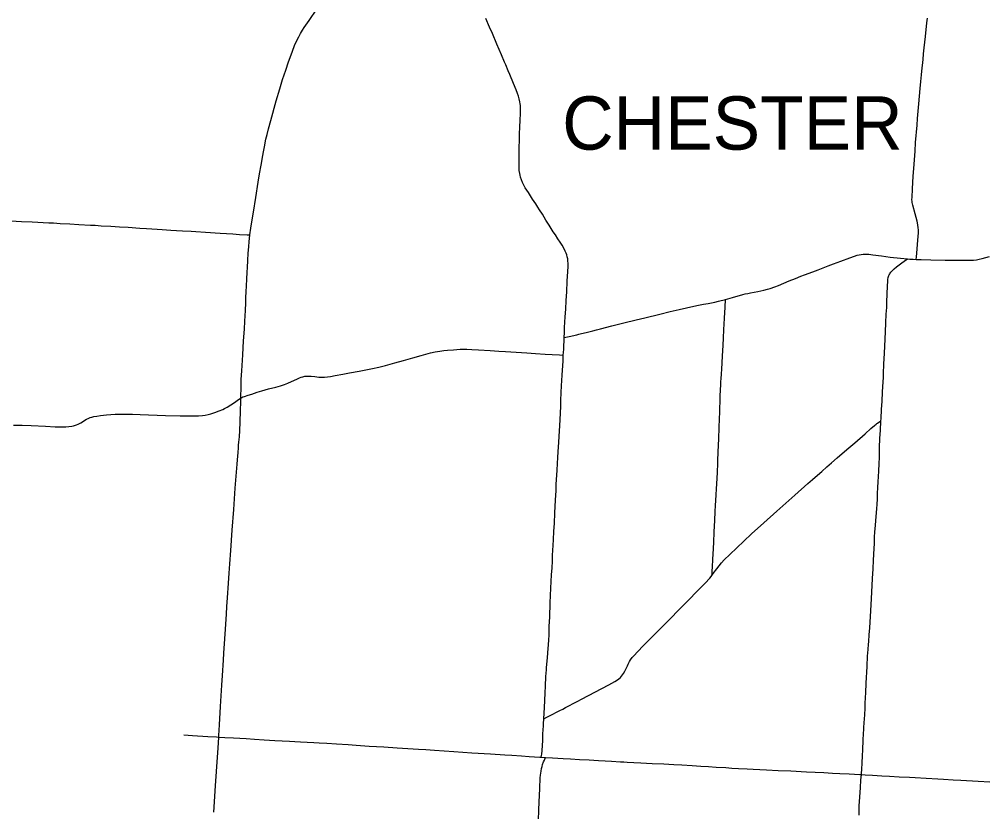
# Model space of a CAD drawing. Extents: x 9078 to 9739, y 4248 to 4966.
# Drawn here: x 9549.3 to 9630.7, y 4427 to 4493.9 of the extents above; entities that cross this region are included whole.
import ezdxf

# ---------------------------------------------------------------- set-up
doc = ezdxf.new("R2010")
doc.units = 0
for name, color, linetype in [('GM_X_County_Road', 7, 'Continuous'), ('GM_X_State_Route', 7, 'Continuous'), ('GM_X_Township_Road', 7, 'Continuous'), ('GM_X_Township_Text', 7, 'Continuous')]:
    doc.layers.add(name, color=color, linetype=linetype)

msp = doc.modelspace()

# ---------------------------------------------------------------- linework, layer by layer
at = {"layer": 'GM_X_County_Road'}
for points in [[(9625.055, 4473.625), (9625.073, 4473.844), (9625.128, 4474.495), (9625.167, 4474.902), (9625.226, 4475.555), (9625.246, 4475.882), (9625.245, 4476.127), (9625.234, 4476.29), (9625.2, 4476.534), (9625.132, 4476.854), (9624.971, 4477.489), (9624.784, 4478.203), (9624.729, 4478.442), (9624.715, 4478.523), (9624.702, 4478.685), (9624.705, 4478.849), (9624.749, 4479.585), (9624.808, 4480.646), (9624.852, 4481.297), (9624.96, 4482.766), (9625.012, 4483.502), (9625.13, 4484.971), (9625.173, 4485.543), (9625.271, 4486.767), (9625.394, 4488.072), (9625.447, 4488.642), (9625.507, 4489.212), (9625.541, 4489.538), (9625.636, 4490.515), (9625.683, 4491.004), (9625.735, 4491.493), (9625.787, 4491.981), (9625.839, 4492.468), (9625.963, 4493.608), (9626.009, 4494.015)], [(9548.102, 4476.916), (9549.494, 4476.839), (9550.395, 4476.793), (9551.788, 4476.726), (9552.197, 4476.707), (9552.77, 4476.673), (9553.589, 4476.629), (9554.326, 4476.587), (9555.308, 4476.532), (9555.718, 4476.507), (9556.208, 4476.476), (9557.025, 4476.426), (9557.761, 4476.389), (9558.497, 4476.338), (9559.48, 4476.278), (9560.052, 4476.235), (9560.952, 4476.177), (9561.361, 4476.15), (9562.097, 4476.103), (9562.588, 4476.071), (9563.079, 4476.04), (9563.815, 4475.998), (9564.225, 4475.978), (9565.044, 4475.929), (9566.271, 4475.848), (9567.335, 4475.777), (9567.907, 4475.734), (9568.563, 4475.697), (9568.791, 4475.69)], [(9608.942, 4470.226), (9609.547, 4470.397), (9610.41, 4470.66), (9610.602, 4470.708), (9610.834, 4470.755), (9611.052, 4470.796), (9611.696, 4470.923), (9612.178, 4471.024), (9612.497, 4471.103), (9612.732, 4471.174), (9613.12, 4471.308), (9613.426, 4471.427), (9614.336, 4471.804), (9614.866, 4472.023), (9615.321, 4472.202), (9615.627, 4472.319), (9616.317, 4472.581), (9616.778, 4472.753), (9617.62, 4473.074), (9618.08, 4473.248), (9618.694, 4473.479), (9619.463, 4473.764), (9619.849, 4473.904), (9620.083, 4473.981), (9620.242, 4474.021), (9620.404, 4474.048), (9620.567, 4474.066), (9620.813, 4474.075), (9621.059, 4474.062), (9621.385, 4474.025), (9622.116, 4473.921), (9622.849, 4473.827), (9623.745, 4473.72), (9624.317, 4473.664)], [(9625.055, 4473.625), (9625.463, 4473.61), (9626.283, 4473.588), (9627.514, 4473.566), (9628.006, 4473.568), (9629.154, 4473.55), (9629.647, 4473.552), (9629.893, 4473.565), (9630.137, 4473.592), (9630.38, 4473.634), (9630.619, 4473.69), (9631.249, 4473.875)], [(9624.317, 4473.664), (9624.52, 4473.649), (9624.808, 4473.634), (9625.055, 4473.625)], [(9595.329, 4467.041), (9595.75, 4467.116), (9596.391, 4467.261), (9596.551, 4467.298), (9596.791, 4467.355), (9597.19, 4467.453), (9597.747, 4467.597), (9598.065, 4467.68), (9598.383, 4467.762), (9599.338, 4468.004), (9600.373, 4468.268), (9601.41, 4468.521), (9602.129, 4468.696), (9603.407, 4469.005), (9604.286, 4469.219), (9605.046, 4469.408), (9605.647, 4469.531), (9606.531, 4469.719), (9607.094, 4469.833), (9607.499, 4469.902), (9608.064, 4470.014), (9608.372, 4470.086), (9608.942, 4470.226)], [(9595.255, 4465.533), (9595.271, 4465.759), (9595.284, 4466.032), (9595.329, 4467.041)], [(9568.02, 4461.916), (9568.115, 4461.973), (9568.193, 4462.01), (9568.32, 4462.053), (9568.635, 4462.149), (9568.951, 4462.253), (9569.407, 4462.414), (9569.797, 4462.532), (9570.348, 4462.683), (9570.983, 4462.843), (9571.38, 4462.951), (9571.692, 4463.054), (9571.998, 4463.173), (9572.299, 4463.305), (9572.741, 4463.519), (9572.962, 4463.621), (9573.113, 4463.677), (9573.268, 4463.72), (9573.427, 4463.749), (9573.589, 4463.764), (9573.748, 4463.765), (9573.881, 4463.761), (9573.954, 4463.757), (9574.272, 4463.724), (9574.599, 4463.688), (9574.847, 4463.675), (9575.094, 4463.679), (9575.34, 4463.7), (9575.585, 4463.734), (9575.988, 4463.811), (9576.631, 4463.936), (9577.195, 4464.037), (9578.002, 4464.181), (9579.125, 4464.417), (9579.686, 4464.537), (9580.244, 4464.673), (9580.639, 4464.781), (9581.033, 4464.892), (9581.743, 4465.088), (9582.534, 4465.304), (9583.242, 4465.509), (9583.635, 4465.62), (9584.03, 4465.722), (9584.429, 4465.806), (9584.831, 4465.876), (9585.154, 4465.922), (9585.479, 4465.957), (9585.968, 4465.997), (9586.539, 4466.031), (9586.865, 4466.039), (9587.11, 4466.036), (9587.518, 4466.018), (9588.09, 4465.982), (9589.072, 4465.92), (9589.808, 4465.878), (9590.379, 4465.835), (9591.279, 4465.783), (9592.179, 4465.728), (9592.915, 4465.684), (9593.732, 4465.632), (9594.305, 4465.598), (9594.937, 4465.553), (9595.255, 4465.533)], [(9566.153, 4433.28), (9566.654, 4433.24), (9567.388, 4433.201), (9567.927, 4433.169), (9568.481, 4433.144), (9569.177, 4433.102), (9569.993, 4433.052), (9570.883, 4432.992), (9571.515, 4432.95), (9572.142, 4432.918), (9572.584, 4432.895), (9573.045, 4432.872), (9573.626, 4432.84), (9574.193, 4432.808), (9574.636, 4432.784), (9575.295, 4432.757), (9576.093, 4432.715), (9577.075, 4432.637), (9577.767, 4432.591), (9578.858, 4432.517), (9580.087, 4432.439), (9581.233, 4432.363), (9582.134, 4432.3), (9583.036, 4432.246), (9583.64, 4432.213), (9584.378, 4432.163), (9586.015, 4432.057), (9587.536, 4431.953), (9589.091, 4431.855), (9590.319, 4431.775), (9590.892, 4431.736), (9591.709, 4431.68), (9592.364, 4431.634), (9593.264, 4431.577), (9593.396, 4431.57)], [(9593.396, 4431.57), (9593.418, 4431.569), (9593.757, 4431.55)], [(9593.757, 4431.55), (9594.342, 4431.516), (9595.246, 4431.455), (9595.85, 4431.423), (9596.621, 4431.379), (9597.429, 4431.339), (9598.223, 4431.294), (9598.79, 4431.263), (9599.311, 4431.236), (9600.072, 4431.191), (9600.378, 4431.178), (9600.641, 4431.156), (9601.214, 4431.126), (9601.787, 4431.099), (9602.768, 4431.047), (9603.755, 4431.009), (9604.593, 4430.96), (9605.271, 4430.924), (9606.146, 4430.862), (9606.862, 4430.823), (9607.517, 4430.784), (9608.172, 4430.741), (9608.991, 4430.693), (9609.481, 4430.662), (9610.052, 4430.633), (9610.788, 4430.594), (9611.279, 4430.568), (9612.426, 4430.508), (9613.409, 4430.464), (9614.473, 4430.414), (9615.784, 4430.343), (9617.245, 4430.274), (9617.976, 4430.234), (9618.614, 4430.207), (9619.382, 4430.171), (9620.309, 4430.109), (9620.432, 4430.103)], [(9620.432, 4430.103), (9620.76, 4430.087), (9621.358, 4430.051), (9622.161, 4430.006), (9622.794, 4429.975), (9623.624, 4429.926), (9624.489, 4429.882), (9624.958, 4429.855), (9625.889, 4429.797), (9626.871, 4429.749), (9627.367, 4429.721), (9628.179, 4429.674), (9628.833, 4429.639), (9630.302, 4429.555), (9631.284, 4429.494), (9632.431, 4429.433), (9633.004, 4429.396), (9633.823, 4429.349), (9634.059, 4429.334)]]:
    msp.add_lwpolyline(points, dxfattribs=at)
at = {"layer": 'GM_X_State_Route'}
msp.add_lwpolyline([(9565.734, 4426.937), (9565.882, 4429.147), (9565.967, 4430.373), (9566.019, 4431.192), (9566.099, 4432.337), (9566.153, 4433.28), (9566.16, 4433.401), (9566.215, 4434.302), (9566.314, 4435.857), (9566.425, 4437.657), (9566.47, 4438.476), (9566.548, 4439.785), (9566.587, 4440.358), (9566.669, 4441.582), (9566.722, 4442.401), (9566.797, 4443.66), (9566.838, 4444.319), (9566.885, 4445.039), (9566.972, 4446.274), (9567.028, 4447.129), (9567.08, 4447.921), (9567.167, 4449.025), (9567.297, 4450.742), (9567.414, 4452.496), (9567.481, 4453.412), (9567.553, 4454.308), (9567.657, 4455.645), (9567.702, 4456.336), (9567.733, 4456.707), (9567.779, 4457.319), (9567.81, 4457.71), (9567.829, 4457.931), (9567.853, 4458.175), (9567.892, 4458.626), (9567.923, 4459.182), (9567.96, 4459.883), (9567.996, 4460.866), (9568.015, 4461.604), (9568.02, 4461.916), (9568.039, 4462.916), (9568.058, 4463.491), (9568.092, 4464.204), (9568.185, 4465.553), (9568.257, 4466.747), (9568.326, 4467.746), (9568.364, 4468.401), (9568.407, 4469.301), (9568.433, 4469.957), (9568.448, 4470.449), (9568.461, 4470.858), (9568.486, 4471.432), (9568.514, 4471.923), (9568.552, 4472.578), (9568.571, 4472.905), (9568.607, 4473.559), (9568.641, 4474.132), (9568.684, 4474.705), (9568.723, 4475.113), (9568.791, 4475.69), (9568.868, 4476.252), (9568.98, 4476.982), (9569.081, 4477.63), (9569.271, 4478.846), (9569.484, 4480.141), (9569.606, 4480.869), (9569.736, 4481.596), (9569.882, 4482.403), (9569.94, 4482.726), (9570.012, 4483.128), (9570.139, 4483.77), (9570.229, 4484.17), (9570.349, 4484.648), (9570.54, 4485.361), (9571.008, 4487.019), (9571.31, 4488.042), (9571.55, 4488.827), (9571.805, 4489.607), (9572.044, 4490.306), (9572.183, 4490.692), (9572.381, 4491.23), (9572.564, 4491.687), (9572.729, 4492.062), (9572.909, 4492.431), (9573.065, 4492.72), (9573.231, 4493.004), (9573.364, 4493.211), (9573.783, 4493.819), (9574.423, 4494.772)], dxfattribs=at)
at = {"layer": 'GM_X_Township_Road'}
for points in [[(9595.329, 4467.041), (9595.344, 4467.463), (9595.365, 4467.872), (9595.416, 4468.77), (9595.453, 4469.423), (9595.496, 4470.159), (9595.541, 4470.896), (9595.588, 4471.796), (9595.632, 4472.614), (9595.65, 4473.024), (9595.652, 4473.271), (9595.642, 4473.518), (9595.623, 4473.683), (9595.589, 4473.845), (9595.544, 4474.004), (9595.488, 4474.16), (9595.423, 4474.312), (9595.312, 4474.533), (9595.149, 4474.817), (9594.978, 4475.089), (9594.803, 4475.356), (9594.581, 4475.694), (9594.405, 4475.967), (9594.23, 4476.243), (9594.059, 4476.52), (9593.767, 4476.954), (9593.486, 4477.437), (9593.233, 4477.828), (9593.104, 4478.035), (9592.928, 4478.307), (9592.659, 4478.717), (9592.302, 4479.267), (9592.043, 4479.684), (9591.924, 4479.898), (9591.819, 4480.118), (9591.725, 4480.345), (9591.646, 4480.575), (9591.604, 4480.731), (9591.573, 4480.89), (9591.539, 4481.132), (9591.519, 4481.376), (9591.511, 4481.621), (9591.515, 4482.194), (9591.532, 4483.095), (9591.551, 4483.666), (9591.566, 4484.239), (9591.586, 4484.811), (9591.613, 4485.384), (9591.637, 4485.958), (9591.647, 4486.367), (9591.639, 4486.614), (9591.623, 4486.779), (9591.594, 4486.941), (9591.536, 4487.182), (9591.467, 4487.419), (9591.386, 4487.651), (9591.266, 4487.956), (9591.045, 4488.485), (9590.729, 4489.242), (9590.603, 4489.544), (9590.389, 4490.074), (9590.297, 4490.301), (9590.045, 4490.903), (9589.652, 4491.802), (9589.265, 4492.706), (9589.033, 4493.231), (9588.704, 4493.981)], [(9622.081, 4459.98), (9622.092, 4460.157), (9622.133, 4460.976), (9622.176, 4461.629), (9622.22, 4462.447), (9622.24, 4462.856), (9622.286, 4463.671), (9622.301, 4463.998), (9622.33, 4464.771), (9622.372, 4465.715), (9622.401, 4466.288), (9622.461, 4467.517), (9622.494, 4468.255), (9622.534, 4468.991), (9622.565, 4469.564), (9622.587, 4470.056), (9622.646, 4471.367), (9622.66, 4471.776), (9622.675, 4471.939), (9622.703, 4472.101), (9622.723, 4472.181), (9622.749, 4472.258), (9622.78, 4472.334), (9622.817, 4472.407), (9622.86, 4472.477), (9622.907, 4472.544), (9623.015, 4472.667), (9623.195, 4472.835), (9623.385, 4472.991), (9623.85, 4473.328), (9624.045, 4473.477), (9624.317, 4473.664)], [(9607.804, 4446.931), (9607.816, 4447.07), (9607.837, 4447.307), (9607.85, 4447.633), (9607.885, 4448.293), (9607.91, 4448.734), (9607.958, 4449.725), (9608.004, 4450.626), (9608.054, 4451.569), (9608.092, 4452.324), (9608.118, 4452.829), (9608.17, 4453.711), (9608.197, 4454.276), (9608.217, 4454.631), (9608.243, 4455.172), (9608.266, 4455.583), (9608.282, 4455.842), (9608.297, 4456.175), (9608.316, 4456.607), (9608.341, 4457.383), (9608.381, 4458.463), (9608.418, 4459.416), (9608.451, 4460.153), (9608.473, 4460.725), (9608.483, 4461.05), (9608.5, 4461.621), (9608.514, 4462.03), (9608.535, 4462.673), (9608.548, 4462.981), (9608.552, 4463.061), (9608.564, 4463.308), (9608.578, 4463.547), (9608.603, 4463.958), (9608.634, 4464.367), (9608.708, 4465.447), (9608.758, 4466.395), (9608.787, 4466.975), (9608.817, 4467.7), (9608.842, 4468.142), (9608.872, 4468.653), (9608.917, 4469.593), (9608.942, 4470.226)], [(9593.615, 4434.822), (9593.641, 4435.3), (9593.665, 4435.787), (9593.687, 4436.36), (9593.712, 4437.015), (9593.737, 4437.588), (9593.786, 4438.405), (9593.821, 4438.945), (9593.837, 4439.151), (9593.904, 4439.957), (9593.964, 4440.773), (9593.992, 4441.052), (9594.026, 4441.507), (9594.046, 4441.869), (9594.051, 4442.165), (9594.064, 4442.655), (9594.104, 4443.391), (9594.154, 4444.619), (9594.212, 4445.847), (9594.264, 4446.993), (9594.299, 4447.565), (9594.331, 4448.137), (9594.353, 4448.629), (9594.37, 4449.038), (9594.419, 4449.937), (9594.465, 4450.672), (9594.497, 4451.327), (9594.539, 4452.227), (9594.596, 4453.291), (9594.637, 4454.11), (9594.661, 4454.599), (9594.728, 4455.824), (9594.766, 4456.396), (9594.802, 4456.887), (9594.828, 4457.378), (9594.872, 4458.196), (9594.977, 4460.079), (9595.032, 4461.225), (9595.054, 4461.717), (9595.079, 4462.371), (9595.105, 4462.943), (9595.158, 4463.843), (9595.228, 4465.07), (9595.255, 4465.533)], [(9548.821, 4459.635), (9549.559, 4459.622), (9550.297, 4459.59), (9551.526, 4459.532), (9552.345, 4459.49), (9552.837, 4459.477), (9553.247, 4459.48), (9553.493, 4459.497), (9553.737, 4459.53), (9553.897, 4459.564), (9553.975, 4459.587), (9554.128, 4459.647), (9554.276, 4459.717), (9554.495, 4459.832), (9554.992, 4460.12), (9555.137, 4460.195), (9555.288, 4460.259), (9555.443, 4460.311), (9555.602, 4460.352), (9555.844, 4460.397), (9556.17, 4460.439), (9556.66, 4460.489), (9557.396, 4460.544), (9557.806, 4460.56), (9558.133, 4460.56), (9558.87, 4460.54), (9559.525, 4460.516), (9561.657, 4460.448), (9562.888, 4460.424), (9563.462, 4460.416), (9564.036, 4460.414), (9564.445, 4460.426), (9564.773, 4460.445), (9565.017, 4460.473), (9565.259, 4460.517), (9565.497, 4460.579), (9565.808, 4460.684), (9566.192, 4460.829), (9566.493, 4460.957), (9566.639, 4461.031), (9566.852, 4461.154), (9567.475, 4461.551), (9567.722, 4461.712), (9567.91, 4461.841), (9568.02, 4461.916)], [(9607.804, 4446.931), (9607.92, 4447.089), (9608.206, 4447.489), (9608.406, 4447.748), (9608.617, 4447.998), (9608.842, 4448.237), (9609.309, 4448.698), (9609.901, 4449.262), (9610.493, 4449.823), (9611.159, 4450.432), (9612.197, 4451.362), (9613.297, 4452.346), (9614.821, 4453.716), (9615.919, 4454.702), (9616.292, 4455.023), (9616.724, 4455.4), (9617.094, 4455.723), (9617.521, 4456.105), (9617.891, 4456.428), (9618.387, 4456.858), (9619.193, 4457.555), (9619.875, 4458.145), (9620.74, 4458.9), (9621.23, 4459.337), (9621.538, 4459.606), (9621.665, 4459.71), (9621.731, 4459.758), (9621.8, 4459.802), (9622.081, 4459.98)], [(9620.432, 4430.103), (9620.441, 4430.221), (9620.464, 4430.537), (9620.492, 4431.104), (9620.524, 4431.702), (9620.553, 4432.202), (9620.583, 4433.018), (9620.616, 4433.573), (9620.635, 4433.915), (9620.644, 4434.073), (9620.671, 4434.477), (9620.708, 4435.153), (9620.737, 4435.704), (9620.76, 4436.113), (9620.788, 4436.608), (9620.803, 4437.013), (9620.841, 4437.832), (9620.916, 4439.223), (9620.957, 4440.124), (9620.974, 4440.368), (9621.001, 4440.693), (9621.035, 4441.1), (9621.053, 4441.345), (9621.095, 4441.917), (9621.132, 4442.49), (9621.189, 4443.473), (9621.272, 4444.947), (9621.372, 4446.667), (9621.42, 4447.486), (9621.462, 4448.222), (9621.506, 4449.206), (9621.524, 4449.615), (9621.548, 4450.188), (9621.572, 4450.596), (9621.613, 4451.166), (9621.672, 4451.897), (9621.719, 4452.549), (9621.75, 4452.957), (9621.778, 4453.366), (9621.803, 4453.857), (9621.825, 4454.349), (9621.85, 4454.84), (9621.902, 4455.737), (9621.931, 4456.39), (9621.951, 4456.881), (9621.959, 4457.373), (9621.961, 4457.701), (9621.995, 4458.52), (9622.031, 4459.175), (9622.081, 4459.98)], [(9593.615, 4434.822), (9593.869, 4434.946), (9594.376, 4435.209), (9594.688, 4435.367), (9594.961, 4435.511), (9595.219, 4435.645), (9595.436, 4435.76), (9595.72, 4435.913), (9596.152, 4436.133), (9596.49, 4436.32), (9596.786, 4436.48), (9599.104, 4437.701), (9599.61, 4437.973), (9599.82, 4438.1), (9599.951, 4438.199), (9600.071, 4438.311), (9600.179, 4438.434), (9600.325, 4438.632), (9600.455, 4438.841), (9600.567, 4439.059), (9600.665, 4439.285), (9600.725, 4439.437), (9600.843, 4439.652), (9600.931, 4439.791), (9601.076, 4439.989), (9601.232, 4440.18), (9601.512, 4440.483), (9602.017, 4441), (9602.454, 4441.441), (9602.973, 4441.964), (9603.436, 4442.428), (9603.956, 4442.951), (9604.419, 4443.415), (9604.88, 4443.88), (9605.508, 4444.527), (9605.856, 4444.874), (9606.543, 4445.577), (9606.941, 4445.99), (9607.224, 4446.287), (9607.622, 4446.7), (9607.727, 4446.826), (9607.804, 4446.931)], [(9593.396, 4431.57), (9593.416, 4431.718), (9593.43, 4431.823), (9593.465, 4432.152), (9593.494, 4432.562), (9593.516, 4432.973), (9593.533, 4433.547), (9593.553, 4433.896), (9593.572, 4434.212), (9593.594, 4434.511), (9593.606, 4434.701), (9593.615, 4434.822)], [(9563.207, 4433.455), (9563.926, 4433.409), (9565.218, 4433.325), (9565.975, 4433.288), (9566.153, 4433.28)], [(9593.152, 4426.237), (9593.192, 4427.121), (9593.219, 4427.777), (9593.268, 4428.923), (9593.312, 4429.823), (9593.332, 4430.067), (9593.373, 4430.392), (9593.418, 4430.633), (9593.457, 4430.791), (9593.506, 4430.948), (9593.593, 4431.177), (9593.658, 4431.324), (9593.69, 4431.397), (9593.757, 4431.55)], [(9620.239, 4426.675), (9620.251, 4427.472), (9620.3, 4428.208), (9620.354, 4429.011), (9620.391, 4429.638), (9620.432, 4430.103)]]:
    msp.add_lwpolyline(points, dxfattribs=at)

# ---------------------------------------------------------------- texts
at = {"layer": 'GM_X_Township_Text'}
msp.add_text('CHESTER', height=4.5, rotation=0.00001, dxfattribs=at).set_placement((9595.158, 4482.898))

doc.saveas('drawing.dxf')
